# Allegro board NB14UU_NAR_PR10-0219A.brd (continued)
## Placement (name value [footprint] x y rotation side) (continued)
CZ128  0.1U_0201_10V6K  [C_0201]  269.49 56.31 270 top
CZ129  0.1U_0201_10V6K  [C_0201]  239.73 36.4 180 top
CZ130  470P_0402_50V7K  [C_0402]  240.48 37.6 90 top
CZ197  470P_0402_50V7K  [C_0402]  275.84 68.2 90 top
CZ198  100P_0402_50V8J  [C_0402]  261.54 81.61 180 top
CZ200  0.1U_0402_25V6K  [C_0402]  278.44 121 90 top
CZ202  0.1U_0201_10V6K  [C_0201]  127.81 130.86 180 top
CZ203  0.1U_0201_10V6K  [C_0201]  124.43 130.06 0 top
CZ204  15P_0402_50V8J  [C_0402]  286.44 40.64 90 top
CZ205  15P_0402_50V8J  [C_0402]  289.11 40.64 90 top
CZ206  100P_0402_50V8J~D  [C_0402]  288.22 40.64 90 top
CZ207  100P_0402_50V8J~D  [C_0402]  287.33 40.64 90 top
CZ216  0.1U_0201_10V6K  [C_0201]  280.68 73.35 180 top
CZ217  0.1U_0201_10V6K  [C_0201]  283.79 82.62 270 top
CZ218  2.2U_0603_10V6K  [C_0603]  239.2 111.94 270 top
CZ220  0.1U_0402_25V6K  [C_0402]  132.06 122.08 0 top
CZ303  0.1U_0201_10V6K  [C_0201]  171.32 68.15 180 top
CZ305  0.1U_0201_10V6K  [C_0201]  257.11 32.75 270 top
CZ306  470P_0402_50V7K  [C_0402]  255.46 32.79 270 top
CZ309  0.1U_0201_10V6K  [C_0201]  280.27 120.27 90 top
CZ310  0.1U_0201_10V6K  [C_0201]  275.43 92.78 180 top
CZ311  100P_0201_25V8J  [C_0201]  229.24 40.08 90 top
CZ312  100P_0201_25V8J  [C_0201]  226.6 40.38 90 top
CZ313  100P_0201_25V8J  [C_0201]  227.68 36.07 180 top
CZ314  100P_0201_25V8J  [C_0201]  231.35 40.05 90 top
CZ315  100P_0402_50V8J  [C_0402]  222.89 86.43 180 top
CZ316  100P_0402_50V8J  [C_0402]  224.52 82.75 0 top
CZ317  0.1U_0402_25V6  [C_0402]  263.28 56.79 180 top
CZ318  47P_0402_50V8J  [C_0402]  263.28 55.83 180 top
CZ319  2.2P_0402_50V8C  [C_0402]  263.28 54.89 180 top
CZ320  0.1U_0402_25V6  [C_0402]  281.24 89.42 270 top
CZ321  1U_0402_25V6K  [C_0402]  282.18 89.42 270 top
CZ322  100P_0402_50V8J  [C_0402]  283.09 89.42 270 top
DA1  AZ5123-02S.R7G_SOT23-3  [L03ESDL5V0CC3-2_SOT23-3]  299.88 32.52 270 top
DA2  AZ5125-02S.R7G 3P C/A SOT23  [L03ESDL5V0CC3-2_SOT23-3]  299.91 32.52 90 bottom
DA3  AZ5123-02S.R7G_SOT23-3  [L03ESDL5V0CC3-2_SOT23-3]  299.91 37.79 90 bottom
DA4  -  [1N4148WS-L_SOD323-2]  292.79 58.11 90 top
DA5  -  [1N4148WS-L_SOD323-2]  294.44 58.11 90 top
DA6  AZ5125-02S.R7G 3P C/A SOT23  [L03ESDL5V0CC3-2_SOT23-3]  289.75 33.01 0 top
DA7  AZ5125-02S.R7G 3P C/A SOT23  [L03ESDL5V0CC3-2_SOT23-3]  285.81 33.01 0 top
DA8  RB751S40T1G_SOD523-2  [RB520SM-30T2R_EMD2-2]  278.42 44.9 0 top
DC1  RB751540_SOD523  [RB520SM-30T2R_EMD2-2]  200.6 75.72 0 top
DC2  RB751540_SOD523  [RB520SM-30T2R_EMD2-2]  202.3 74.51 180 top
DC4  -  [RB521CM-30T2R_SOD923-2]  205.21 102.05 180 bottom
DE1  BZV55-B5V6_SOD80C2  [BZV55-B5V1_SOD80C2]  85.15 54.93 0 bottom
DE2  RB751S40T1G_SOD523-2  [RB520SM-30T2R_EMD2-2]  244.57 124.66 0 top
DE22  -  [CEST523NC5VB_SOT-523-3]  82.46 59.47 270 top
DI1  -  [AZ1045-04F_DFN2510P10E-10-9]  18.96 88.67 90 bottom
DI2  -  [AZC199-02SPR7G_SOT23-3]  25.87 89.86 90 top
DI3  -  [AZC199-02SPR7G_SOT23-3]  298.76 52.12 180 bottom
DI4  -  [AZ1045-04F_DFN2510P10E-10-9]  300.09 67.49 270 bottom
DI5  -  [AZC199-02SPR7G_SOT23-3]  298.15 64.08 90 top
DI6  -  [AZ1045-04F_DFN2510P10E-10-9]  300.22 50.22 270 bottom
DT1  -  [1N4148WS-7-F_SOD323-2]  59.95 123.9 0 top
DT2  -  [1N4148WS-7-F_SOD323-2]  59.95 122.12 0 top
DT3  -  [1N4148WS-7-F_SOD323-2]  59.95 120.22 0 top
DT4  -  [L30ESD24VC3-2_SOT23-3]  24.8 97.93 90 top
DT5  DESD3V3Z1BCSF-7 X2-DSN0603-2  [ESD8011MUT5G_X3DFN2-2]  14.8 103.89 270 bottom
DT6  DESD3V3Z1BCSF-7 X2-DSN0603-2  [ESD8011MUT5G_X3DFN2-2]  14.8 104.6 90 bottom
DT9  DESD3V3Z1BCSF-7 X2-DSN0603-2  [ESD8011MUT5G_X3DFN2-2]  15.88 107.62 90 bottom
DT10  DESD3V3Z1BCSF-7 X2-DSN0603-2  [ESD8011MUT5G_X3DFN2-2]  15.88 106.91 270 bottom
DT13  DESD3V3Z1BCSF-7 X2-DSN0603-2  [ESD8011MUT5G_X3DFN2-2]  14.8 103.89 270 top
DT14  DESD3V3Z1BCSF-7 X2-DSN0603-2  [ESD8011MUT5G_X3DFN2-2]  14.8 104.6 90 top
DT17  DESD3V3Z1BCSF-7 X2-DSN0603-2  [ESD8011MUT5G_X3DFN2-2]  15.88 107.62 90 top
DT18  DESD3V3Z1BCSF-7 X2-DSN0603-2  [ESD8011MUT5G_X3DFN2-2]  15.88 106.91 270 top
DT39  -  [AZ1045-04F_DFN2510P10E-10-9]  20.63 100.22 90 top
DT40  -  [AZ1045-04F_DFN2510P10E-10-9]  20.63 102.22 270 bottom
DT41  -  [AZ1045-04F_DFN2510P10E-10-9]  283.27 116.69 90 top
DT42  -  [AZ1045-04F_DFN2510P10E-10-9]  283.27 119.77 90 top
DV1  -  [BAT54CW_SOT323-3]  138.11 133.11 180 top
DV2  -  [BAT54CW_SOT323-3]  140.9 133.11 180 top
DV3  -  [BAT54CW_SOT323-3]  157.48 131.58 0 top
DV11  RB751S40T1G_SOD523-2  [RB520SM-30T2R_EMD2-2]  139.34 130.38 180 top
DV12  RB751S40T1G_SOD523-2  [RB520SM-30T2R_EMD2-2]  143.7 130.8 90 top
DV13  AZ5125-02S.R7G 3P C/A SOT23  [L03ESDL5V0CC3-2_SOT23-3]  123.43 126.36 0 top
DV14  -  [AZC199-02SPR7G_SOT23-3]  136.61 127.2 90 top
DZ1  RB751S40T1G_SOD523-2  [RB520SM-30T2R_EMD2-2]  265.03 46.17 0 top
DZ2  RB751S40T1G_SOD523-2  [RB520SM-30T2R_EMD2-2]  265.03 44.9 0 top
DZ5  RB751S40T1G_SOD523-2  [RB520SM-30T2R_EMD2-2]  262.57 83.22 270 top
DZ6  RB751S40T1G_SOD523-2  [RB520SM-30T2R_EMD2-2]  266.38 83.35 270 top
DZ8  -  [RB751S40T1G_SOD523-2]  224.54 37.5 270 top
DZ9  -  [BAT54CW_SOT323-3]  266.5 72.4 180 top
DZ10  -  [AZC199-02SPR7G_SOT23-3]  118.42 124.43 180 top
DZ11  -  [AZC199-02SPR7G_SOT23-3]  296.25 115.2 90 top
DZ12  RB751S40T1G_SOD523-2  [RB520SM-30T2R_EMD2-2]  241.65 113.23 180 top
DZ13  -  [AZ1045-04F_DFN2510P10E-10-9]  300.48 22.28 270 top
FD1  FIDUCIAL MARK~D  [FIDUCIAL_C40M80]  21.14 112.21 0 top
FD2  FIDUCIAL MARK~D  [FIDUCIAL_C40M80]  306 2.74 0 top
FD3  FIDUCIAL MARK~D  [FIDUCIAL_C40M80]  42.74 113.07 180 bottom
FD4  FIDUCIAL MARK~D  [FIDUCIAL_C40M80]  306 2.8 180 bottom
FV1  1A_65V_T0603FF1000TM  [F_T0603FF1000TM]  123.35 130.67 180 top
FZ1  1A_65V_T0603FF1000TM  [F_T0603FF1000TM]  97.89 129.56 90 bottom
FZ2  1A_65V_T0603FF1000TM  [F_T0603FF1000TM]  135.01 134.73 270 top
FZ3  1A_65V_T0603FF1000TM  [F_T0603FF1000TM]  131.22 128.32 90 top
FZ4  1A_65V_T0603FF1000TM  [F_T0603FF1000TM-NPM]  130.9 126.95 180 top
FZ5  1A_65V_T0603FF1000TM  [F_T0603FF1000TM-NPM]  127.59 126.21 90 top
H1  -  [H_4P0]  128.53 111.5 0 top
H2  -  [H_4P0]  192.52 111.5 0 top
H3  -  [H_4P0]  128.53 86.5 0 top
H4  -  [H_4P0]  192.52 86.5 0 top
H7  -  [H_3P2]  268.82 120 0 top
H8  -  [H_3P2]  281.95 67.05 0 top
H11  -  [H_3P3]  118.32 129 0 top
H12  -  [H_3P3]  152.72 129 0 top
H13  H_3P0  [H_3P0-G]  315.03 4 0 top
H14  H_4P0  [H_4P0-G]  301.03 76.5 0 top
H15  -  [H_3P3]  301.52 120 0 top
H16  H_2P6  [H_2P6-G]  249.53 134 0 top
H17  -  [H_3P8]  159.52 136 0 top
H18  H_2P6  [H_2P6-G]  69.52 134 0 top
H20  H_2P6  [H_2P6-G]  15.93 112.4 0 top
H21  -  [H_2P1N]  299.52 43 0 top
H22  -  [H_5P0N]  159.52 32.35 0 top
H25  H_4P0  [H_4P0-G]  80.52 33 0 top
H26  H_4P0  [H_4P0-G]  77.52 91.2 0 top
H27  -  [H_3P1X2P1N]  8.02 80 0 top
H28  H_4P0  [H_4P0-G]  258.53 26.5 0 top
H29  H_4P0  [H_4P0-G]  291.02 120.5 0 top
H30  H_2P6  [H_2P6-G]  3.02 79.5 0 top
JAPS1  ACES_50506-01841-P01  [ACES_50506-01841-P01_18P]  245.74 84.15 180 bottom
JDB1  JXT_FP241AH-006GAAM  [JXT_FP241AH-006GAAM_6P]  33.31 88.93 180 bottom
JDEG1  JXT_FP241AH-010GAAM  [JXT_FP241AH-010GAAM_10P]  218.97 82.87 180 bottom
JDIMM1  LOTES_ADDR0206-P001A  [FOX_ASAA821-H4RB5-7H_260P]  101.45 55.01 180 bottom
JDIMM2  LOTES_ADDR0206-P001A  [FOX_ASAA821-H4RB5-7H_260P]  178.85 51.01 180 bottom
JEDP1  ACES_50398-04041-001  [ACES_50398-04041-001_40P]  125.77 131.02 0 bottom
JESPI  JXT_FP241AH-010GAAM  [JXT_FP241AH-010GAAM_10P]  227.99 82.87 180 bottom
JFAN1  ACES_50271-0040N-001  [ACES_50271-0040N-001_4P]  77.12 64.3 180 bottom
JFPBTN1  FOX_QT510166-L010-7H  [FOX_QT510166-L010-7H_16P]  307.87 116.35 270 bottom
JHDMI1  YUQIU_HD074-F19M1BR-C  [YUQIU_HD074-F19M1BR-C_19P-T]  307.45 89.65 270 bottom
JHP1  SINGA_2SJ3095-136111F~D  [SINGA_2SJ3095-136111F_6P]  306.25 39.35 90 bottom
JIRTS1  ACES_50208-01001-P03  [ACES_50208-01001-P03_10P]  110.22 133.5 180 bottom
JKBTP1  HRS_TF31-20S-0P5SH-800  [HRS_TF31-20S-0P5SH-800_20P-T]  183.49 39.9 0 bottom
JLED1  HRS_TF31-6S-0P5SH  [HRS_TF31-6S-0P5SH_6P-T]  309.07 10.65 180 bottom
JLOM1  SINGA_2RJ3081-1C8211F  [SINGA_2RJ3081-1C8211F_12P-T]  306.2 100.28 90 top
JNGFF1  LOTES_APCI0128-P005A  [LOTES_APCI0128-P005A_75P]  272.7 33.52 0 bottom
JNGFF2  BELLW_80149-3221  [BELLW_80149-3221_67P]  259.58 74.47 0 bottom
JNGFF3  LOTES_APCI0079-P005A  [LOTES_APCI0079-P005A_75P]  282.82 28.77 180 bottom
JRTC1  ACES_50271-0020N-001  [ACES_50271-0020N-001_2P]  239.72 121.2 0 bottom
JSATA1  GS12206-10100-7H  [FOX_GS12206-10100-7H_20P-T]  244.04 38.52 0 bottom
JSD1  T-SOL_158-1240902600  [T-SOL_158-1240902600_23P-T]  304.6 22.86 90 top
JSIM1  JAE_SF51S006V4DR1000Q  [JAE_SF51S006V4DR1000Q_8P]  303.28 24.83 270 bottom
JSPI1  ACES_50506-02041-P01  [ACES_50506-02041-P01_20P]  208.58 84.4 180 bottom
JSPK1  ACES_50278-00401-001  [ACES_50278-00401-001_4P]  293.81 28.14 180 bottom
JTAG1  @SHORT PADS~D  [SHORTPADS]  246.44 105.74 180 top
JUSB1  C-K_26230A-8K1A-02~D  [C-K_26230A-8K1A-02_9P]  302.93 62.9 270 bottom
JUSB2  C-K_26230A-8K1A-02~D  [C-K_26230A-8K1A-02_9P]  16.12 94.2 90 bottom
JUSB3  C-K_26230A-8K1A-02~D  [C-K_26230A-8K1A-02_9P]  302.93 45.7 270 bottom
JUSBC1  JAE_DX07SD24JJ2R1300~D  [JAE_DX07SD24JJ2R1300_24P]  7.35 109.82 270 top
JUSH1  HRS_TF31C-26S-0P5SH-800  [HRS_TF31C-26S-0P5SH-800_26P-T]  224.27 39.9 0 bottom
JXDP1  JXT_FP270H-061G1AM  [JXT_FP270H-061G1AM_61P]  76.17 134.19 0 bottom
LA5  BLM15PX600SN1D_2P  [MURAT_BLM15PX600SN1D_2P]  290.06 61.62 90 top
LA6  BLM15PX800SN1D_2P  [MURAT_BLM15PD800SN1D_2P]  290.51 37.71 270 top
LA7  BLM15PX800SN1D_2P  [MURAT_BLM15PD800SN1D_2P]  288.79 37.71 270 top
LA8  BLM15PX800SN1D_2P  [MURAT_BLM15PD800SN1D_2P]  286.76 37.71 270 top
LA9  BLM15PX800SN1D_2P  [MURAT_BLM15PD800SN1D_2P]  284.86 37.71 270 top
LA10  BLM15PX330SN1D_2P  [MURAT_BLM15PX330SN1D_2P]  298.06 34.45 90 bottom
LA11  BLM15PX330SN1D_2P  [MURAT_BLM15PX330SN1D_2P]  296.38 38.57 90 bottom
LA12  BLM15PX600SN1D_2P  [MURAT_BLM15PX600SN1D_2P]  289.05 48.31 270 top
LA13  HCB2012KF-121T50_2P  [TAI-T_HCB2012KF-121T50_2P]  277.13 53.54 180 top
LA14  BLM15PX600SN1D_2P  [MURAT_BLM15PX600SN1D_2P]  280.98 47.74 270 top
LA15  BLM15PX330SN1D_2P  [MURAT_BLM15PX330SN1D_2P]  297.24 32.25 270 top
LA16  BLM15PX330SN1D_2P  [MURAT_BLM15PX330SN1D_2P]  297.24 33.68 90 top
LC1  LQM18PN2R2NC0L_2P~D  [MURAT_BLM18EG221SN1D_2P]  174.89 118.67 270 top
LC2  LQM18PN2R2NC0L_2P~D  [MURAT_BLM18EG221SN1D_2P]  196.3 117.46 180 bottom
LC3  LQM18PN2R2NC0L_2P~D  [MURAT_BLM18EG221SN1D_2P]  175.45 125.34 180 top
LC4  BLM18EG221TN1D_2P~D  [MURAT_BLM18EG221SN1D_2P]  194.59 97.22 180 top
LC5  BLM15BD121SN1D_2P~D  [MURAT_BLM15BD121SN1D_2P]  185.56 119.83 0 bottom
LC6  HCB1608KF-121T30  [MURAT_BLM18EG221SN1D_2P]  99.74 130.76 270 bottom
LC7  HCB1608KF-121T30  [MURAT_BLM18EG221SN1D_2P]  146.9 135.33 0 top
LC8  HCB1608KF-121T30  [MURAT_BLM18EG221SN1D_2P]  220.32 88.62 90 top
LC9  HCB1608KF-121T30  [MURAT_BLM18EG221SN1D_2P]  264.74 36.62 0 top
LC10  HCB1608KF-121T30  [MURAT_BLM18EG221SN1D_2P]  277.32 94.29 90 top
LC11  HCB1608KF-121T30  [MURAT_BLM18EG221SN1D_2P]  94.89 130.39 90 top
LC12  HCB1608KF-121T30  [MURAT_BLM18EG221SN1D_2P]  218.85 88.62 90 top
LED3  LTW-C193DC-C_WHITE  [LED_LTW-C193DC-C_2P]  310.38 121.75 0 top
LGA1  -  [LNG2DMTR_LGA12_2X2]  250.17 35.29 270 top
LI3  DLM0NSN900HY2D_4P  [MURAT_DLM0NSN900HY2D_4P]  27.28 91.39 180 top
LI4  DLM0NSN900HY2D_4P  [MURAT_DLM0NSN900HY2D_4P]  298.39 56.63 270 bottom
LI7  DLM0NSN900HY2D_4P  [MURAT_DLM0NSN900HY2D_4P]  292.79 66.41 270 top
LI8  MCM1012B900F06BP_4P  [INPAQ_MCM1012B900F06BP_4P]  263.63 72.61 180 bottom
LI9  MCM1012B900F06BP_4P  [INPAQ_MCM1012B900F06BP_4P-NPM]  267.3 34.61 270 bottom
LI12  BLM15BB100SN1D  [MURAT_BLM15BD121SN1D_2P]  267.1 34.42 270 bottom
LI13  BLM15BB100SN1D  [MURAT_BLM15BD121SN1D_2P]  267.99 34.42 270 bottom
LI16  HCM1012GH900BP_4P  [INPAQ_HCM1012GH900BP_4P]  262.07 70.56 0 bottom
LI17  HCM1012GH900BP_4P  [INPAQ_HCM1012GH900BP_4P]  261.99 69.04 0 bottom
LL1  4.7UH +-20% MPB201210T-4R7M-NA2  [TAIYO_BRC2012T4R7MD_2P]  272.53 102.26 270 top
LT11  BLM18KG331SN1D_2P  [MURAT_BLM18KG331SN1D_2P]  36.75 107.13 0 top
LT601  BLM18KG331SN1D_2P  [MURAT_BLM18KG331SN1D_2P]  41.08 112.36 270 top
LT602  BLM18KG331SN1D_2P  [MURAT_BLM18KG331SN1D_2P]  39.81 112.36 270 top
LT603  BLM18KG331SN1D_2P  [MURAT_BLM18KG331SN1D_2P]  35.29 102.56 0 top
LT604  BLM18KG331SN1D_2P  [MURAT_BLM18KG331SN1D_2P]  43.62 110.13 270 top
LT605  BLM18KG331SN1D_2P  [MURAT_BLM18KG331SN1D_2P]  35.35 109.23 0 bottom
LV1  BLM15PX221SN1D_2P  [MURAT_BLM15PX221SN1D_2P]  136.33 133 90 top
LV3  DLW21SN900HQ2L_0805_4P  [MURAT_DLW21SN900HQ2L0805_4P-NPM]  300.52 89.22 0 top
LV6  DLW21SN900HQ2L_0805_4P  [MURAT_DLW21SN900HQ2L0805_4P-NPM]  300.52 87.31 0 top
LV9  DLW21SN900HQ2L_0805_4P  [MURAT_DLW21SN900HQ2L0805_4P-NPM]  300.52 85.41 0 top
LV12  DLW21SN900HQ2L_0805_4P  [MURAT_DLW21SN900HQ2L0805_4P-NPM]  300.52 83.5 0 top
LZ1  DLM0NSN900HY2D_4P  [MURAT_DLM0NSN900HY2D_4P]  139.04 128.09 180 top
LZ3  HCB1005KF-600T25  [MURAT_BLM15PD600SN1D_2P]  225.58 38.87 0 top
LZ4  HCB1005KF-600T25  [MURAT_BLM15PD600SN1D_2P]  227.73 37.46 90 top
NOREF  -  []  148.83 67.71 0 top
NOREF#2  -  []  291.02 120.5 0 top
NOREF#3  -  []  15.93 112.4 0 top
NOREF#4  -  []  125.89 68.73 0 top
NOREF#5  -  []  159.52 32.35 0 top
NOREF#6  -  []  192.52 86.5 0 top
NOREF#7  -  []  268.82 120 0 top
NOREF#8  -  []  220.94 117.66 0 top
NOREF#9  -  []  127.85 68.1 0 top
NOREF#10  -  []  301.52 120 0 top
NOREF#11  -  []  315.03 4 0 top
NOREF#12  -  []  69.52 134 0 top
NOREF#13  -  []  157.96 -187.65 0 top
NOREF#14  -  []  192.52 111.5 0 top
NOREF#15  -  []  128.53 111.5 0 top
NOREF#16  -  []  118.32 129 0 top
NOREF#17  -  []  80.52 33 0 top
NOREF#18  -  []  281.95 67.05 0 top
NOREF#19  -  []  152.72 129 0 top
NOREF#20  -  []  143.45 31.67 0 top
NOREF#21  -  []  128.53 86.5 0 top
NOREF#22  -  []  301.03 76.5 0 top
NOREF#23  -  []  191.26 61.94 0 top
NOREF#24  -  []  169.07 -43.31 0 top
NOREF#25  -  []  77.52 91.2 0 top
NOREF#26  -  []  212.79 58.33 0 top
NOREF#27  -  []  258.53 26.5 0 top
NOREF#28  -  []  197.77 58.01 270 top
NOREF#29  -  []  249.53 134 0 top
NOREF#30  -  []  368.44 -160.33 180 bottom
NOREF#31  -  []  370.91 67.97 180 bottom
NOREF#32  -  []  150.41 73.81 180 bottom
PBATT1  DEREN_40-42251-01001RHF  [DEREN_40-42251-01001RHF_10P-T]  148.77 42.7 180 bottom
PC1  2200P_0402_50V7K  [C_0402]  140.01 39.88 90 top
PC3  1U_0402_25V6K  [C_0402]  239.83 118.5 90 top
PC4  0.022U 25V K X7R 0402  [C_0402]  78.24 111.71 180 bottom
PC5  1000P_0402_50V7K  [C_0402]  68.77 119.53 270 bottom
PC6  0.022U 25V K X7R 0402  [C_0402]  76.04 118.77 90 bottom
PC7  0.1U_0402_25V6  [C_0402]  74.06 118.78 90 bottom
PC8  10U_0603_25V6M  [C_0603]  75.93 114.67 180 bottom
PC10  4.7U_0402_6.3V6M  [C_0402]  68.84 117.42 180 top
PC11  1000P_0402_50V7K  [C_0402]  75.24 117.61 270 top
PC12  82P_0402_50V8J  [C_0402]  68.84 116.53 180 top
PC13  0.1U_0402_10V7K  [C_0402]  78.67 114.42 90 top
PC100  0.1U_0402_25V6  [C_0402]  196.72 33.53 90 bottom
PC102  0.1U_0402_25V6  [C_0402]  205.99 29.79 90 bottom
PC103  100P_0402_50V8J  [C_0402]  201.23 31.18 90 bottom
PC104  10U_0603_25V6M  [C_0603]  200.15 30.62 90 bottom
PC105  10U_0603_25V6M  [C_0603]  200.15 30.62 90 top
PC106  22U_0603_6.3V6M  [C_0603]  219.2 36.4 90 top
PC107  22U_0603_6.3V6M  [C_0603]  219.2 36.4 90 bottom
PC108  22U_0603_6.3V6M  [C_0603]  220.4 36.4 90 bottom
PC109  22U_0603_6.3V6M  [C_0603]  217.99 36.4 90 bottom
PC110  22U_0603_6.3V6M  [C_0603]  220.4 36.4 90 top
PC111  4.7U_0402_6.3V6M  [C_0402]  205.8 38.38 270 bottom
PC112  680P_0402_50V7K  [C_0402]  201.8 34.87 180 top
PC113  1000P_0402_50V7K  [C_0402]  203.51 37.4 90 bottom
PC114  0.1U_0402_25V6  [C_0402]  85.02 73.98 90 bottom
PC115  0.1U_0402_25V6  [C_0402]  81.03 67.76 180 top
PC116  2200P_0402_50V7K  [C_0402]  81.03 66.88 180 top
PC117  10U_0603_25V6M  [C_0603]  81.28 68.91 180 top
PC118  10U_0603_25V6M  [C_0603]  81.28 68.91 180 bottom
PC119  2.2U 6.3V M X5R 0402  [C_0402]  76.34 73.99 180 bottom
PC120  22U_0603_6.3V6M  [C_0603]  74.99 76.46 270 top
PC121  22U_0603_6.3V6M  [C_0603]  76.26 76.46 270 top
PC122  22U_0603_6.3V6M  [C_0603]  76.26 76.46 270 bottom
PC123  22U_0603_6.3V6M  [C_0603]  73.72 76.46 270 bottom
PC124  22U_0603_6.3V6M  [C_0603]  74.99 76.46 270 bottom
PC125  680P_0402_50V7K  [C_0402]  86.42 81.16 90 bottom
PC126  4.7U_0402_6.3V6M  [C_0402]  76.34 73.1 180 bottom
PC127  1000P_0402_50V7K  [C_0402]  76.34 71.57 180 bottom
PC128  4.7U_0402_6.3V6M  [C_0402]  76.26 70.64 270 bottom
PC129  22U_0603_6.3V6M  [C_0603]  217.99 36.4 90 top
PC130  22U_0603_6.3V6M  [C_0603]  73.72 76.46 270 top
PC131  82P_0402_50V8J  [C_0402]  201.23 31.18 90 top
PC132  82P_0402_50V8J  [C_0402]  81.03 67.76 180 bottom
PC133  100P_0402_50V8J  [C_0402]  198.56 33.53 90 bottom
PC134  100P_0402_50V8J  [C_0402]  197.67 33.53 90 bottom
PC135  100P_0402_50V8J  [C_0402]  215.7 36.45 90 bottom
PC136  27P_0402_50V8J  [C_0402]  215.7 36.45 90 top
PC137  100P_0402_50V8J  [C_0402]  72.58 76.48 270 top
PC138  100P_0402_50V8J  [C_0402]  72.58 76.48 270 bottom
PC139  100P_0402_50V8J  [C_0402]  81.03 65.97 180 top
PC140  100P_0402_50V8J  [C_0402]  81.03 65.07 180 top
PC141  1U_0402_25V6K  [C_0402]  179.57 31.24 90 bottom
PC142  1U_0402_25V6K  [C_0402]  85.66 69.56 270 bottom
PC143  100P_0402_50V8J  [C_0402]  198.65 31.06 90 top
PC145  100P_0402_50V8J  [C_0402]  78.58 76.4 270 top
PC146  22P_0402_50V8J  [C_0402]  86.62 69.57 270 bottom
PC161  22U_0603_6.3V6M  [C_0603]  216.78 36.4 90 bottom
PC162  22U_0603_6.3V6M  [C_0603]  216.78 36.4 90 top
PC163  22U_0603_6.3V6M  [C_0603]  77.53 76.46 270 top
PC164  22U_0603_6.3V6M  [C_0603]  77.53 76.46 270 bottom
PC200  10U_0603_25V6M  [C_0603]  91.38 69.54 0 top
PC201  10U_0603_25V6M  [C_0603]  91.38 69.54 0 bottom
PC202  82P_0402_50V8J  [C_0402]  91.44 70.62 0 top
PC203  0.1U_0402_25V6  [C_0402]  91.44 70.62 0 bottom
PC204  680P_0402_50V7K  [C_0402]  90.86 66.93 90 top
PC205  0.1U_0402_25V6  [C_0402]  85.97 62.18 270 bottom
PC206  1U_0201_6.3V6M  [C_0201]  88.43 64.27 180 bottom
PC207  2.2U 6.3V M X5R 0402  [C_0402]  88.46 65.54 180 bottom
PC208  330P_0402_50V7K  [C_0402]  87.61 67.83 0 bottom
PC209  22U_0603_6.3V6M  [C_0603]  94.81 64.12 0 bottom
PC210  22U_0603_6.3V6M  [C_0603]  95.31 55.83 270 top
PC211  22U_0603_6.3V6M  [C_0603]  95.31 55.83 270 bottom
PC212  22U_0603_6.3V6M  [C_0603]  94.04 55.83 270 top
PC213  22U_0603_6.3V6M  [C_0603]  94.04 55.83 270 bottom
PC214  10U_0603_10V6M  [C_0603]  92.77 55.83 270 top
PC216  15P_0402_50V8J  [C_0402]  96.39 55.4 270 top
PC217  15P_0402_50V8J  [C_0402]  96.39 55.4 270 bottom
PC218  1U_0201_6.3V6M  [C_0201]  94.79 66.9 270 bottom
PC219  22U_0603_6.3V6M  [C_0603]  94.8 65.38 0 bottom
PC221  0.1U_0402_10V7K  [C_0402]  95.19 70.37 180 bottom
PC222  0.1U_0402_10V7K  [C_0402]  95.26 69.54 180 top
PC223  10U_0603_10V6M  [C_0603]  92.77 55.83 270 bottom
PC224  100P_0402_50V8J  [C_0402]  91.69 55.4 270 top
PC225  100P_0402_50V8J  [C_0402]  91.69 55.4 270 bottom
PC226  1U_0201_6.3V6M  [C_0201]  219.9 30.34 270 bottom
PC227  1U_0201_6.3V6M  [C_0201]  95.36 66.9 270 bottom
PC228  22P 16V K X7R 0201  [C_0201]  221.06 30.34 270 bottom
PC301  18P 50V K NPO 0402  [C_0402]  234.17 125.74 0 bottom
PC302  680P_0402_50V7K  [C_0402]  227.13 130.38 0 bottom
PC303  100P_0402_50V8J  [C_0402]  234.17 126.63 0 bottom
PC304  0.1U_0402_25V6  [C_0402]  230.06 126.44 90 top
PC305  10U_0603_25V6M  [C_0603]  233.11 127.71 0 top
PC306  10U_0603_25V6M  [C_0603]  233.11 127.71 0 bottom
PC307  330P_0402_50V7K  [C_0402]  231.82 135.46 0 top
PC308  22U_0603_6.3V6M  [C_0603]  219.71 132.09 90 top
PC309  22U_0603_6.3V6M  [C_0603]  219.71 132.09 90 bottom
PC310  22U_0603_6.3V6M  [C_0603]  220.98 132.09 90 bottom
PC311  22U_0603_6.3V6M  [C_0603]  220.98 132.09 90 top
PC312  1U_0201_6.3V6M  [C_0201]  230.94 134.22 270 top
PC313  2.2U 6.3V M X5R 0402  [C_0402]  230.06 133.73 90 top
PC314  1U_0201_6.3V6M  [C_0201]  220.47 29.75 90 bottom
PC315  100P_0402_50V8J  [C_0402]  232.33 114.34 0 top
PC316  0.1U_0402_25V6  [C_0402]  232.33 115.28 0 top
PC317  1U_0402_25V6K  [C_0402]  232.33 116.23 0 top
PC318  27P_0402_50V8J  [C_0402]  217.74 132.71 90 top
PC319  100P_0402_50V8J  [C_0402]  218.63 132.71 90 top
PC320  1U_0402_25V6K  [C_0402]  216.85 132.71 90 top
PC330  120P_0402_50V8J  [C_0402]  234.16 124.84 0 bottom
PC331  100P_0402_50V8J  [C_0402]  229.92 125.37 180 top
PC332  100P_0402_50V8J  [C_0402]  227.77 124.38 90 bottom
PC333  1U_0402_25V6K  [C_0402]  229.67 124.37 90 bottom
PC334  18p_0402_50V6  [C_0402]  232.33 117.17 0 top
PC335  0.1U_0402_25V6  [C_0402]  228.72 124.37 90 bottom
PC336  0.1U_0402_25V6  [C_0402]  230.68 127.84 0 bottom
PC337  1U_0402_25V6K  [C_0402]  230.67 126.88 0 bottom
PC338  0.1U_0402_25V6  [C_0402]  232.56 125.04 90 bottom
PC339  0.1U_0402_25V6  [C_0402]  230.67 125.93 0 bottom
PC350  0.022U_ 0402_25V7K  [C_0402]  235.34 130.33 270 top
PC360  0.1U_0402_25V6  [C_0402]  235.31 132.89 0 top
PC401  470P_0402_50V7K  [C_0402]  110.42 78.89 270 top
PC402  0.1U_0402_25V6  [C_0402]  104.78 72.46 180 top
PC403  10U_0603_10V6M  [C_0603]  102.67 74.31 270 top
PC404  10U_0603_10V6M  [C_0603]  101.4 74.31 270 top
PC406  22U_0603_6.3V6M  [C_0603]  110.04 72.53 270 top
PC407  22U_0603_6.3V6M  [C_0603]  108.77 72.53 270 top
PC408  0.1U_0402_25V6  [C_0402]  99.25 74.32 270 top
PC409  100P_0402_50V8J  [C_0402]  100.26 74.32 270 top
PC410  1U_0402_25V6K  [C_0402]  207.96 126.18 90 bottom
PC411  0.1U_0402_25V6  [C_0402]  209.42 133.92 90 top
PC412  10U_0603_10V6M  [C_0603]  212.09 132.03 90 top
PC413  10U_0603_10V6M  [C_0603]  212.09 132.03 90 bottom
PC414  0.1U_0402_25V6  [C_0402]  208.87 126.17 90 bottom
PC415  22U_0603_6.3V6M  [C_0603]  201.1 132.09 90 top
PC416  100P_0402_50V8J  [C_0402]  210.61 126.69 135 bottom
PC417  0.1U_0402_25V6  [C_0402]  213.16 132.01 90 bottom
PC418  2200P_0402_50V7K  [C_0402]  213.16 132.01 90 top
PC419  680P_0402_50V7K  [C_0402]  206.55 130.57 0 bottom
PC420  22P_0402_50V8J  [C_0402]  211.01 132.05 90 bottom
PC421  0.1U_0402_25V6  [C_0402]  210.05 132.05 90 bottom
PC424  22U_0603_6.3V6M  [C_0603]  201.1 132.09 90 bottom
PC425  10U_0402_6.3V6M  [C_0402]  112.2 72.54 270 top
PC426  10U_0402_6.3V6M  [C_0402]  111.18 72.54 270 top
PC427  10U_0402_6.3V6M  [C_0402]  202.24 132.33 90 bottom
PC428  10U_0402_6.3V6M  [C_0402]  202.24 132.33 90 top
PC501  22U_0603_6.3V6M  [C_0603]  199.83 109.67 0 top
PC503  68P_0402_50V8J  [C_0402]  203.96 109.15 90 bottom
PC504  22U_0603_6.3V6M  [C_0603]  199.83 109.67 0 bottom
PC505  .1U_0402_16V7K  [C_0402]  201.48 111.66 270 top
PC506  680P_0402_50V7K  [C_0402]  200.45 114.88 0 bottom
PC507  4.7U_0402_6.3V6M  [C_0402]  281.92 95.58 0 top
PC508  4.7U_0402_6.3V6M  [C_0402]  281.92 94.69 0 top
PC509  0.01UF_0402_25V7K  [C_0402]  286.63 96.52 90 top
PC510  0.1U_0402_25V6  [C_0402]  280.03 98.87 90 top
PC511  22U_0603_6.3V6M  [C_0603]  285.72 95.39 180 top
PC513  .1U_0402_16V7K  [C_0402]  243.54 62.45 0 top
PC514  4.7U_0402_6.3V6M  [C_0402]  240.82 61.57 270 top
PC515  0.01UF_0402_25V7K  [C_0402]  242.98 55.83 90 top
PC516  22U_0603_6.3V6M  [C_0603]  240.56 57.62 90 top
PC517  4.7U_0402_6.3V6M  [C_0402]  239.67 61.57 270 top
PC530  22U_0603_6.3V6M  [C_0603]  202.67 114.69 0 bottom
PC601  680P_0402_50V7K  [C_0402]  96.41 93.7 90 top
PC602  0.1U_0402_25V6  [C_0402]  87.65 101.45 90 bottom
PC603  4.7U_0402_6.3V6M  [C_0402]  91.33 101.45 90 top
PC604  1U_0402_25V6K  [C_0402]  92.79 101.27 0 top
PC605  47P_0402_50V8J  [C_0402]  84.31 102.31 0 top
PC606  100U_D_20VM_R55M  [C_D]  93.21 107.51 90 bottom
PC607  100U_D_20VM_R55M  [C_D]  88.51 107.51 90 bottom
PC608  10U 25V M X5R 0603 ZRB  [C_0603-S3]  178.05 129.74 180 top
PC611  0.22U 25V K X5R 0402  [C_0402]  180.27 131.58 270 top
PC612  10U 25V M X5R 0603 ZRB  [C_0603-S3]  178.05 129.74 180 bottom
PC613  330P_0402_50V7K  [C_0402]  85.75 100.2 270 top
PC614  2200P_0402_50V7K  [C_0402]  87.43 95.76 90 bottom
PC616  68P 50V J NPO 0402  [C_0402]  86.55 95.76 90 bottom
PC617  1200P_0402_50V7K  [C_0402]  81.94 97.89 90 top
PC618  330P_0402_50V7K  [C_0402]  80.92 97.91 270 top
PC619  0.01UF_0402_25V7K  [C_0402]  80.92 95.22 90 top
PC620  0.082U_0402_16V7K  [C_0402]  81.94 97.03 270 top
PC621  680P_0402_50V7K  [C_0402]  83 99.74 0 top
PC622  680P_0402_50V7K  [C_0402]  178.62 131.9 90 bottom
PC624  0.022U_0402_25V7K  [C_0402]  83.84 95.37 270 top
PC625  330P_0402_50V7K  [C_0402]  86.38 89 90 top
PC626  0.1U_0402_25V6  [C_0402]  82.95 95.37 270 top
PC627  2200P_0402_50V7K  [C_0402]  85.62 93.83 90 top
PC628  33P_0402_50V8J  [C_0402]  92.81 96.7 180 bottom
PC629  2200P_0402_50V7K  [C_0402]  88.96 94.89 270 bottom
PC630  2200P_0402_50V7K  [C_0402]  94.25 92.71 270 top
PC631  4700P_0402_25V7K  [C_0402]  92.81 97.58 180 bottom
PC632  1000P_0402_50V7K  [C_0402]  94.51 97.89 90 top
PC633  4700P 25V K X7R 0402  [C_0402]  172.55 129.47 180 top
PC635  0.022U_0402_16V7K  [C_0402]  85.24 91.29 90 top
PC636  33P_0402_50V8J  [C_0402]  90.48 94.89 270 bottom
PC637  0.033U_0402_25V7K  [C_0402]  96.29 97.89 90 top
PC638  0.022U_0402_16V7K  [C_0402]  86.13 91.29 90 top
PC639  1500P_0402_50V7K  [C_0402]  89.89 89.84 180 top
PC640  2200P_0402_50V7K  [C_0402]  95.4 95.48 90 top
PC641  .1U_0402_16V7K  [C_0402]  82.95 93.6 270 top
PC642  0.068U_0402_16V7K  [C_0402]  91.51 92.76 0 top
PC643  330P_0402_50V7K  [C_0402]  92.81 95.81 180 bottom
PC644  .1U_0402_16V7K  [C_0402]  96.21 99.74 0 top
PC645  .1U_0402_16V7K  [C_0402]  92.6 90.8 270 top
PC646  6800P 50V K X7R 0402  [C_0402]  91.51 91.74 0 top
PC647  680P_0402_50V7K  [C_0402]  88.03 89.91 270 top
PC649  0.01UF_0402_25V7K  [C_0402]  97.43 96.37 90 top
PC650  0.082U_0402_16V7K  [C_0402]  96.41 96.52 270 top
PC651  330P_0402_50V7K  [C_0402]  89.86 88.95 0 top
PC652  330P_0402_50V7K  [C_0402]  97.43 95.5 270 top
PC653  0.082U_0402_16V7K  [C_0402]  90.75 89.84 0 top
PC654  0.01UF_0402_25V7K  [C_0402]  92.55 88.95 180 top
PC655  0.22U_0402_25V6K  [C_0402]  114.11 96.47 90 bottom
PC656  10U 25V M X5R 0603 ZRB  [C_0603-S3]  110.23 100.72 90 bottom
PC657  10U 25V M X5R 0603 ZRB  [C_0603-S3]  110.23 100.72 90 top
PC658  10U 25V M X5R 0603 ZRB  [C_0603-S3]  111.44 100.72 90 top
PC659  0.1U_0402_25V6  [C_0402]  112.52 101.22 90 top
PC660  2200P_0402_50V7K  [C_0402]  109.15 101.22 90 bottom
PC661  4.7U_0402_6.3V6M  [C_0402]  120.01 100.96 90 bottom
PC662  680P_0402_50V7K  [C_0402]  113.53 105.74 180 top
PC663  0.22U_0402_25V6K  [C_0402]  101.28 90.11 0 bottom
PC664  10U 25V M X5R 0603 ZRB  [C_0603-S3]  105.41 93.99 0 bottom
PC665  10U 25V M X5R 0603 ZRB  [C_0603-S3]  105.41 93.99 0 top
PC666  100P_0402_50V8J  [C_0402]  105.33 90.74 0 top
PC667  1U_0402_25V6K  [C_0402]  105.33 91.7 0 top
PC668  4.7U_0402_6.3V6M  [C_0402]  105.84 84.2 0 bottom
PC669  4.7U_0402_6.3V6M  [C_0402]  102.48 86.69 90 bottom
PC670  680P_0402_50V7K  [C_0402]  110.87 89.86 180 top
PC671  0.22U_0402_25V6K  [C_0402]  100.13 101.42 90 bottom
PC672  10U 25V M X5R 0603 ZRB  [C_0603-S3]  96.2 106.98 90 bottom
PC673  10U 25V M X5R 0603 ZRB  [C_0603-S3]  96.2 106.97 90 top
PC674  10U 25V M X5R 0603 ZRB  [C_0603-S3]  105.41 92.78 0 top
PC675  10U 25V M X5R 0603 ZRB  [C_0603-S3]  105.41 92.78 0 bottom
PC676  4.7U_0402_6.3V6M  [C_0402]  117.47 97.67 180 bottom
PC677  4.7U_0402_6.3V6M  [C_0402]  103.51 102.58 180 bottom
PC678  680P_0402_50V7K  [C_0402]  99.44 110.06 180 top
PC682  10U 25V M X5R 0603 ZRB  [C_0603-S3]  111.44 100.72 90 bottom
PC683  10U 25V M X5R 0603 ZRB  [C_0603-S3]  97.4 106.97 90 bottom
PC684  10U 25V M X5R 0603 ZRB  [C_0603-S3]  97.39 106.97 90 top
PC685  4.7U_0402_6.3V6M  [C_0402]  182.88 134.87 90 top
PC686  0.1U_0402_25V6  [C_0402]  112.52 101.22 90 bottom
PC687  0.1U_0402_25V6  [C_0402]  105.65 91.7 0 bottom
PC688  0.1U_0402_25V6  [C_0402]  98.5 107.06 90 bottom
PC689  100P_0402_50V8J  [C_0402]  91.8 82.95 90 bottom
PC690  100P_0402_50V8J  [C_0402]  92.76 82.95 90 bottom
PC691  1U_0402_25V6K  [C_0402]  90.85 82.95 90 bottom
PC692  22P_0402_50V8J  [C_0402]  89.9 82.95 90 bottom
PC693  100P_0402_50V8J  [C_0402]  95.11 107 90 top
PC694  18P 50V K 0402  [C_0402]  94.14 107 90 top
PC697  4.7U_0402_6.3V6M  [C_0402]  106.04 105.92 90 bottom
PC700  0.1U_0402_25V6  [C_0402]  100.69 37.5 0 top
PC701  2200P_0402_50V7K  [C_0402]  100.69 36.18 0 top
PC702  10U_0805_25VAK  [C_0805]  100.36 30.87 0 top
PC703  10U_0805_25VAK  [C_0805]  100.36 32.59 0 top
PC704  10U_0805_25VAK  [C_0805]  100.49 39.76 0 top
PC706  10U_0805_25VAK  [C_0805]  100.36 32.59 0 bottom
PC707  10U_0603_25V6M  [C_0603]  124.84 33.22 180 bottom
PC708  10U_0603_25V6M  [C_0603]  124.84 34.49 180 bottom
PC709  10U_0603_25V6M  [C_0603]  124.84 34.49 180 top
PC710  10U_0603_25V6M  [C_0603]  124.84 33.22 180 top
PC715  15U_B2_25VM_R100M  [C_B2]  125.26 30.93 0 bottom
PC716  10U_0805_25VAK  [C_0805]  100.49 39.76 0 bottom
PC717  10U_0805_25VAK  [C_0805]  100.36 30.87 0 bottom
PC719  4.7U_0402_6.3V6M  [C_0402]  81.9 43.06 0 bottom
PC720  0.1U_0402_25V6  [C_0402]  124.72 36.53 180 top
PC721  2200P_0402_50V7K  [C_0402]  124.72 39.17 180 top
PC725  1U_0402_25V6K  [C_0402]  81.87 42.15 180 bottom
PC726  1U_0402_25V6K  [C_0402]  82.74 42.15 0 bottom
PC727  0.47U 25V K X5R 0402  [C_0402]  86.05 41.96 270 bottom
PC728  0.1U_0201_25V6K  [C_0201]  125.83 42.01 45 top
PC729  0.1U_0201_25V6K  [C_0201]  123.57 40.97 225 top
PC730  0.1U_0201_25V6K  [C_0201]  125.43 42.41 45 top
PC731  82P_0201_50V8J  [C_0201]  123.14 41.4 225 top
PC732  82P_0201_50V8J  [C_0201]  125.01 42.83 45 top
PC733  82P_0201_50V8J  [C_0201]  121.05 41.73 270 top
PC734  22P 16V K X7R 0201  [C_0201]  124.59 43.26 45 top
PC735  2200P 16V K X7R 0201  [C_0201]  121.64 41.73 270 top
PC736  0.1U_0402_25V6  [C_0402]  81.66 46.91 0 top
PC737  2.2U_0402_25V6M  [C_0402]  79.81 43.13 90 top
PC738  4.7U_0402_6.3V6M  [C_0402]  87.69 44.05 0 bottom
PC739  4.7U_0402_6.3V6M  [C_0402]  88.59 43.13 270 bottom
PC740  0.47U 25V K X5R 0402  [C_0402]  88.53 46.85 0 bottom
PC741  10U_0603_25V6M  [C_0603]  128.77 39.8 90 top
PC742  10U_0603_25V6M  [C_0603]  128.77 39.8 90 bottom
PC743  4700P_0402_25V7K  [C_0402]  130.22 36.14 0 top
PC744  10P_0402_50V8J  [C_0402]  81.71 48.59 0 top
PC745  0.1U_0402_25V6  [C_0402]  88.45 48.75 0 bottom
PC746  680P_0402_50V7K  [C_0402]  104.96 42.62 270 bottom
PC747  680P_0402_50V7K  [C_0402]  122.42 41.86 0 bottom
PC748  1U_0402_25V6K  [C_0402]  88.07 50.73 0 bottom
PC749  560P_0402_50V7K  [C_0402]  84.21 50.84 90 bottom
PC750  0.1U_0402_25V6  [C_0402]  85.1 50.84 90 bottom
PC751  0.01UF_0402_25V7K  [C_0402]  82.42 51.67 0 bottom
PC752  1U_0402_25V6K  [C_0402]  88.1 49.83 180 bottom
PC753  0.22U_0402_25V6K  [C_0402]  87.21 50.73 180 bottom
PC754  0.1U_0402_10V7K  [C_0402]  76.39 42.16 90 bottom
PC755  0.1U_0402_25V6  [C_0402]  85.42 49.11 270 top
PC756  100P_0402_50V8J  [C_0402]  100.76 41.09 0 bottom
PC760  100P_0402_50V8J  [C_0402]  124.62 30.69 180 top
PC761  18p_0402_50V6  [C_0402]  124.75 37.84 180 top
PC800  100P_0402_50V8J  [C_0402]  54.11 85.93 180 bottom
PC801  0.01UF_0402_25V7K  [C_0402]  60.59 84.15 180 bottom
PC802  1500P_0402_50V7K  [C_0402]  77.72 110.81 90 top
PC803  0.47U 25V K X5R 0402  [C_0402]  68.98 106.88 0 top
PC804  220P_0402_50V8J  [C_0402]  56.02 88.72 180 bottom
PC805  1200P_0402_50V7K  [C_0402]  56.65 83.77 180 bottom
PC806  100P_0402_50V8J  [C_0402]  19.88 95.16 180 top
PC807  1000P_0402_50V7K  [C_0402]  19.88 96.05 180 top
PC808  0.1U_0402_25V6  [C_0402]  20.07 91.96 180 top
PC809  100P_0402_50V8J  [C_0402]  20.07 92.85 180 top
PC810  1500P_0402_50V7K  [C_0402]  48.83 91.31 90 top
PC811  10U_0402_6.3V M  [C_0402]  61.53 87.5 90 bottom
PC812  100P_0402_50V8J  [C_0402]  59.67 88.59 0 bottom
PC813  2.2U_0402_25V6M  [C_0402]  61.53 85.88 270 bottom
PC814  0.1U_0402_10V7K  [C_0402]  83.62 103.02 270 bottom
PC865  0.1U_0402_25V6  [C_0402]  89.22 114.43 270 top
PC1000  22U_0603_6.3V6M  [C_0603]  164.52 101.8 270 top
PC1001  22U_0603_6.3V6M  [C_0603]  163.32 101.8 270 top
PC1002  22U_0603_6.3V6M  [C_0603]  122.04 111.33 0 bottom
PC1003  22U_0603_6.3V6M  [C_0603]  122.04 111.33 0 top
PC1004  22U_0603_6.3V6M  [C_0603]  108.52 110.94 270 top
PC1005  22U_0603_6.3V6M  [C_0603]  108.52 110.94 270 bottom
PC1006  22U_0603_6.3V6M  [C_0603]  122.04 112.6 0 top
PC1007  22U_0603_6.3V6M  [C_0603]  122.04 112.6 0 bottom
PC1008  22U_0603_6.3V6M  [C_0603]  162.11 98.05 90 top
PC1009  22U_0603_6.3V6M  [C_0603]  162.11 101.81 270 top
PC1011  22U_0603_6.3V6M  [C_0603]  164.52 98.05 90 top
PC1012  22U_0603_6.3V6M  [C_0603]  156.94 122.47 90 bottom
PC1013  22U_0603_6.3V6M  [C_0603]  160.9 98.05 90 top
PC1014  22U_0603_6.3V6M  [C_0603]  159.7 98.05 90 top
PC1015  22U_0603_6.3V6M  [C_0603]  159.7 101.8 270 top
PC1016  22U_0603_6.3V6M  [C_0603]  155.74 122.47 90 top
PC1017  22U_0603_6.3V6M  [C_0603]  155.74 122.47 90 bottom
PC1018  22U_0603_6.3V6M  [C_0603]  160.9 101.79 270 top
PC1019  22U_0603_6.3V6M  [C_0603]  163.32 98.05 90 top
PC1020  22U_0603_6.3V6M  [C_0603]  156.94 122.47 90 top
PC1031  1U_0201_6.3V6M  [C_0201]  161.32 94.18 180 top
PC1032  1U_0201_6.3V6M  [C_0201]  165.63 104.79 0 top
PC1033  1U_0201_6.3V6M  [C_0201]  161.95 94.18 0 top
PC1034  1U_0201_6.3V6M  [C_0201]  165.54 94.21 90 top
PC1035  1U_0201_6.3V6M  [C_0201]  164.36 94.18 0 top
PC1036  1U_0201_6.3V6M  [C_0201]  159.32 102.65 90 top
PC1037  1U_0201_6.3V6M  [C_0201]  163.74 94.75 180 top
PC1038  1U_0201_6.3V6M  [C_0201]  164.36 94.75 0 top
PC1039  1U_0201_6.3V6M  [C_0201]  158.91 94.75 180 top
PC1040  1U_0201_6.3V6M  [C_0201]  157.12 94.18 0 top
PC1041  1U_0201_6.3V6M  [C_0201]  162.21 93.61 180 top
PC1042  1U_0201_6.3V6M  [C_0201]  158.91 94.18 180 top
PC1043  1U_0201_6.3V6M  [C_0201]  156.87 105.36 0 top
PC1044  1U_0201_6.3V6M  [C_0201]  153.83 105.36 180 top
PC1045  1U_0201_6.3V6M  [C_0201]  156.24 105.36 180 top
PC1046  1U_0201_6.3V6M  [C_0201]  154.45 104.79 0 top
PC1047  1U_0201_6.3V6M  [C_0201]  153.83 104.79 180 top
PC1048  1U_0201_6.3V6M  [C_0201]  149.63 104.79 0 top
PC1049  1U_0201_6.3V6M  [C_0201]  159.53 94.18 0 top
PC1050  1U_0201_6.3V6M  [C_0201]  159.53 94.75 0 top
PC1051  1U_0201_6.3V6M  [C_0201]  156.87 104.79 0 top
PC1052  1U_0201_6.3V6M  [C_0201]  151.42 104.79 180 top
PC1053  1U_0201_6.3V6M  [C_0201]  152.04 105.36 0 top
PC1054  1U_0201_6.3V6M  [C_0201]  161.69 105.36 0 top
PC1055  1U_0201_6.3V6M  [C_0201]  156.24 104.79 180 top
PC1056  1U_0201_6.3V6M  [C_0201]  154.45 105.36 0 top
PC1057  1U_0201_6.3V6M  [C_0201]  159.28 104.79 0 top
PC1058  1U_0201_6.3V6M  [C_0201]  159.28 105.36 0 top
PC1059  1U_0201_6.3V6M  [C_0201]  158.66 104.79 180 top
PC1060  1U_0201_6.3V6M  [C_0201]  163.22 104.79 0 top
PC1061  1U_0201_6.3V6M  [C_0201]  165.01 105.36 180 top
PC1062  1U_0201_6.3V6M  [C_0201]  161.32 94.75 180 top
PC1063  1U_0201_6.3V6M  [C_0201]  158.66 105.36 180 top
PC1064  1U_0201_6.3V6M  [C_0201]  161.07 104.79 180 top
PC1065  1U_0201_6.3V6M  [C_0201]  161.07 105.36 180 top
PC1066  1U_0201_6.3V6M  [C_0201]  161.69 104.79 0 top
PC1067  1U_0201_6.3V6M  [C_0201]  165.01 104.79 180 top
PC1068  1U_0201_6.3V6M  [C_0201]  157.12 94.75 0 top
PC1069  1U_0201_6.3V6M  [C_0201]  161.95 94.75 0 top
PC1070  1U_0201_6.3V6M  [C_0201]  163.22 105.36 0 top
PC1071  47U_0603_6.3V6M  [C_0603-S3]  151.49 102.94 180 top
PC1072  47U_0603_6.3V6M  [C_0603-S3]  152.45 102.93 0 top
PC1073  47U_0603_6.3V6M  [C_0603-S3]  156.19 102.93 180 top
PC1074  47U_0603_6.3V6M  [C_0603-S3]  157.16 102.94 0 top
PC1075  47U_0603_6.3V6M  [C_0603-S3]  161.51 102.97 180 top
PC1076  47U_0603_6.3V6M  [C_0603-S3]  163.1 102.99 0 top
PC1077  47U_0603_6.3V6M  [C_0603-S3]  157.21 96.96 180 top
PC1078  47U_0603_6.3V6M  [C_0603-S3]  159.2 96.95 0 top
PC1079  47U_0603_6.3V6M  [C_0603-S3]  162.95 96.95 180 top
PC1080  47U_0603_6.3V6M  [C_0603-S3]  164.13 96.96 0 top
PC1081  22U_0603_6.3V6M  [C_0603]  109.72 110.94 270 top
PC1082  22U_0603_6.3V6M  [C_0603]  154.53 122.47 90 bottom
PC1083  22U_0603_6.3V6M  [C_0603]  109.72 110.94 270 bottom
PC1084  22U_0603_6.3V6M  [C_0603]  110.93 110.94 270 top
PC1085  22U_0603_6.3V6M  [C_0603]  154.53 122.47 90 top
PC1086  22U_0603_6.3V6M  [C_0603]  153.32 122.47 90 top
PC1087  22U_0603_6.3V6M  [C_0603]  153.32 122.47 90 bottom
PC1088  22U_0603_6.3V6M  [C_0603]  110.93 110.94 270 bottom
PC1089  1U_0201_6.3V6M  [C_0201]  152.04 104.79 0 top
PC1090  1U_0201_6.3V6M  [C_0201]  163.74 94.18 180 top
PC1091  330U_D2_2.5VM_R9M  [C_D2]  159.9 117.24 90 bottom
PC1092  330U_D3_2.5VY_R6M  [C_D3]  157.18 99.96 180 top
PC1093  330U_D3_2.5VY_R6M  [C_D3]  159.9 117.24 90 top
PC1094  330U_D3_2.5VY_R6M  [C_D3]  155.66 119.07 180 top
PC1096  100P_0201_25V8J  [C_0201]  151.42 105.36 180 top
PC1097  100P_0201_25V8J  [C_0201]  149.63 105.36 0 top
PC1098  100P_0201_25V8J  [C_0201]  122.16 114.15 0 bottom
PC1099  100P_0201_25V8J  [C_0201]  162.85 119.4 0 top
PC1100  100P_0201_25V8J  [C_0201]  122.16 113.52 0 bottom
PC1101  22U_0603_6.3V6M  [C_0603]  121.41 85.82 270 top
PC1102  22U_0603_6.3V6M  [C_0603]  128.89 102.95 90 top
PC1103  22U_0603_6.3V6M  [C_0603]  122.61 85.82 270 bottom
PC1104  22U_0603_6.3V6M  [C_0603]  127.68 102.94 90 bottom
PC1105  22U_0603_6.3V6M  [C_0603]  147.44 98.12 0 top
PC1106  22U_0603_6.3V6M  [C_0603]  143.95 99.32 90 top
PC1107  22U_0603_6.3V6M  [C_0603]  144.65 98.37 270 top
PC1108  22U_0603_6.3V6M  [C_0603]  120.2 85.82 270 bottom
PC1109  22U_0603_6.3V6M  [C_0603]  147.44 101.74 0 top
PC1110  22U_0603_6.3V6M  [C_0603]  145.85 98.37 270 top
PC1111  22U_0603_6.3V6M  [C_0603]  127.67 102.95 90 top
PC1112  22U_0603_6.3V6M  [C_0603]  143.95 103.07 270 top
PC1113  22U_0603_6.3V6M  [C_0603]  120.2 85.82 270 top
PC1114  22U_0603_6.3V6M  [C_0603]  147.44 99.32 0 top
PC1115  22U_0603_6.3V6M  [C_0603]  147.44 102.94 0 top
PC1116  22U_0603_6.3V6M  [C_0603]  147.44 100.53 0 top
PC1117  22U_0603_6.3V6M  [C_0603]  128.89 102.94 90 bottom
PC1118  22U_0603_6.3V6M  [C_0603]  146.36 99.32 90 top
PC1119  22U_0603_6.3V6M  [C_0603]  145.22 105.1 180 top
PC1120  22U_0603_6.3V6M  [C_0603]  121.41 85.82 270 bottom
PC1121  22U_0603_6.3V6M  [C_0603]  145.16 103.07 270 top
PC1122  22U_0603_6.3V6M  [C_0603]  146.36 103.07 270 top
PC1123  22U_0603_6.3V6M  [C_0603]  145.16 99.32 90 top
PC1131  1U_0201_6.3V6M  [C_0201]  147.8 104.79 180 top
PC1132  1U_0201_6.3V6M  [C_0201]  146.01 105.36 0 top
PC1133  1U_0201_6.3V6M  [C_0201]  130.35 103.6 90 bottom
PC1134  1U_0201_6.3V6M  [C_0201]  129.78 103.6 90 bottom
PC1135  1U_0201_6.3V6M  [C_0201]  143.06 102.35 270 top
PC1136  1U_0201_6.3V6M  [C_0201]  148.17 97.23 0 top
PC1137  1U_0201_6.3V6M  [C_0201]  143.06 106.03 270 top
PC1138  1U_0201_6.3V6M  [C_0201]  147.8 105.36 180 top
PC1139  1U_0201_6.3V6M  [C_0201]  146.01 104.79 0 top
PC1140  1U_0201_6.3V6M  [C_0201]  131.49 103.6 90 bottom
PC1141  1U_0201_6.3V6M  [C_0201]  130.92 103.6 90 bottom
PC1142  330U_D3_2.5VY_R6M  [C_D3]  124.73 98.9 90 bottom
PC1143  330U_D3_2.5VY_R6M  [C_D3]  124.72 98.9 90 top
PC1146  100P_0201_25V8J  [C_0201]  148.42 105.36 0 top
PC1147  100P_0201_25V8J  [C_0201]  148.42 104.79 0 top
PC1151  22U_0603_6.3V6M  [C_0603]  166.11 133.36 180 bottom
PC1152  22U_0603_6.3V6M  [C_0603]  166.94 102.84 180 top
PC1153  22U_0603_6.3V6M  [C_0603]  167.64 97.04 0 top
PC1154  22U_0603_6.3V6M  [C_0603]  166.11 133.36 180 top
PC1155  22U_0603_6.3V6M  [C_0603]  167 101.61 180 top
PC1156  22U_0603_6.3V6M  [C_0603]  166.11 132.09 180 top
PC1157  22U_0603_6.3V6M  [C_0603]  166.12 130.86 180 top
PC1158  22U_0603_6.3V6M  [C_0603]  166.11 132.09 180 bottom
PC1159  22U_0603_6.3V6M  [C_0603]  167 100.4 180 top
PC1160  22U_0603_6.3V6M  [C_0603]  166.09 130.88 180 bottom
PC1161  22U_0603_6.3V6M  [C_0603]  167.64 98.24 0 top
PC1166  100P_0201_25V8J  [C_0201]  166.34 103.73 180 top
PC1167  100P_0201_25V8J  [C_0201]  166.78 105.36 180 top
PC1168  100P_0201_25V8J  [C_0201]  165.91 129.03 180 top
PC1169  18p_0402_50V6  [C_0402]  166.2 134.43 180 top
PC1170  22P_0402_50V8J  [C_0402]  167.38 134.16 90 top
PC1171  0.1U_0402_25V6  [C_0402]  165.98 129.78 180 top
PC1200  1000P_0402_50V7K  [C_0402]  150.38 122.98 90 top
PC1201  0.1U_0402_25V6  [C_0402]  151.3 122.98 90 top
PC1202  18p_0402_50V6  [C_0402]  152.22 123.01 90 top
PC1627  68U_D_20VM_R55M  [C_D]  96.06 88.43 180 bottom
PC3001  82P_0201_50V8J  [C_0201]  75.75 35.57 270 top
PC3002  0.01UF 25V +-10% X7R 0402  [C_0402]  71.78 33.08 180 top
PC3003  82P_0201_50V8J  [C_0201]  72.12 36.54 0 top
PC3004  82P_0201_50V8J  [C_0201]  67.14 32.99 0 top
PC3005  0.22U_0402_10V K  [C_0402]  69.74 36.7 0 top
PC3008  1U_0201_6.3V6M  [C_0201]  72.4 30.9 270 top
PC3009  1U_0201_6.3V6M  [C_0201]  73.95 33.73 180 top
PC3010  1U_0201_6.3V6M  [C_0201]  68.59 31.58 180 top
PC3011  1U_0201_6.3V6M  [C_0201]  68.59 30.95 180 top
PD1  CEST523NC5VB_SOT-523-3  [TVNST52302AB0_SOT523-3]  150.75 41.09 270 top
PD2  CEST523NC5VB_SOT-523-3  [TVNST52302AB0_SOT523-3]  150.75 43.13 270 top
PD3  BAS40CW_SOT323-3  [DB3J315E0L_SMINI3-F2-B3]  237.8 118.5 180 top
PD4  AZ5125-02S.R7G_SOT23-3  [PESD5V0U2BT_SOT23-3]  72.96 120.7 0 top
PD5  S SCH DIO 5A 100V 15UA 0.88V TO227-3  [PDS5100H-13_POWERDI5-3]  82.95 115.24 90 bottom
PD700  SDMK0340L-7-F_SOD323-2~D  [SDMK0340L-7-F_SOD323-2]  78.04 50.25 90 top
PD701  -  [SMF4L22A_SOD123FL2]  94.87 43.63 0 bottom
PD702  SDMK0340L-7-F_SOD323-2~D  [SDMK0340L-7-F_SOD323-2]  80.96 50.25 90 top
PD704  -  [RB520SM-30T2R_EMD2-2]  79.5 50.25 90 top
PD705  -  [BAT54CW_SOT323-3]  73.33 46.77 180 bottom
PD800  -  [BAT54CW_SOT323-3]  61.59 82.12 90 bottom
PD801  S SCH DIO 5A 100V 15UA 0.88V TO227-3  [PDS5100H-13_POWERDI5-3]  78.4 106.25 180 top
PD802  -  [SDMK0340L-7-F_SOD323-2]  63.69 87.89 270 bottom
PD803  -  [BAT54CW_SOT323-3]  67.64 115.4 0 top
PD3000  -  [BAT54CW_SOT323-3]  68.07 36.55 180 top
PD3001  -  [RB520SM-30T2R_EMD2-2]  74.86 35.89 270 top
PD3002  -  [RB520SM-30T2R_EMD2-2]  69.22 35.35 270 top
PH601  470K_0402_5%_B25/50 4700K  [R_0402]  119.79 103.31 90 bottom
PH602  10K_0402_5%_B25/50 4250K  [R_0402]  121.22 107.82 90 bottom
PH603  470K_0402_5%_B25/50 4700K  [R_0402]  109.66 91.7 0 bottom
PH604  10KB_0402_5%  [R_0402]  169.91 129.49 0 top
PH605  10K_0402_5%_B25/50 4250K  [R_0402]  114.98 83.51 0 bottom
PJP1  PAD-OPEN1x1m  [JUMP_43X39]  196.22 133.33 270 top
PJP2  PAD-OPEN1x1m  [JUMP_43X39]  190.84 133.17 270 top
PJP3  PAD-OPEN1x3m  [JUMP_43X118]  188.19 129.99 180 top
PJP8  PAD-OPEN 1x3m  [JUMP_43X118]  66.36 97.79 90 bottom
PJP12  PAD-OPEN1x1m  [JUMP_43X39]  146.95 133.53 0 top
PJP14  PAD-OPEN1x1m  [JUMP_43X39]  287 29.16 0 top
PJP15  PAD-OPEN1x1m  [JUMP_43X39]  274.07 56.46 180 top
PJP16  PAD-OPEN1x1m  [JUMP_43X39]  268.3 57.41 180 top
PJP17  PAD-OPEN1x2m  [JUMP_43X79]  274.44 59.81 270 top
PJP18  PAD-OPEN1x1m  [JUMP_43X39]  268.3 59.64 180 top
PJP19  PAD-OPEN1x1m  [JUMP_43X39]  288.09 61.4 90 top
PJP20  PAD-OPEN1x1m  [JUMP_43X39]  261.12 94.31 180 top
PJP22  PAD-OPEN1x1m  [JUMP_43X39]  248.6 85.09 90 top
PJP31  PAD-OPEN1x3m  [JUMP_43X118]  266.49 27.26 90 top
PJP32  PAD-OPEN1x1m  [JUMP_43X39]  239.83 34.07 270 top
PJP33  PAD-OPEN1x1m  [JUMP_43X39]  258.24 33.41 0 bottom
PJP34  PAD-OPEN1x2m  [JUMP_43X79]  250.86 41.09 180 top
PJP35  PAD-OPEN1x1m  [JUMP_43X39]  185.85 36.84 0 top
PJP36  PAD-OPEN1x2m  [JUMP_43X79]  264.6 63.62 270 top
PJP37  PAD-OPEN1x1m  [JUMP_43X39]  275.52 94.23 90 top
PJP38  PAD-OPEN1x1m  [JUMP_43X39]  222.45 82.94 180 top
PJP39  PAD-OPEN1x3m  [JUMP_43X118]  223.64 88.87 90 top
PJP40  PAD-OPEN1x2m  [JUMP_43X79]  271.97 64.05 270 top
PJP41  PAD-OPEN1x3m  [JUMP_43X118]  277.17 87.49 270 top
PJP42  PAD-OPEN1x1m  [JUMP_43X39]  277.55 63.14 270 top
PJP100  PAD-OPEN 1x2m~D  [JUMP_43X79]  196.8 31.19 0 bottom
PJP101  PAD-OPEN 1x2m~D  [JUMP_43X79]  84.05 71.07 180 bottom
PJP102  -  [JUMP_43X118]  218.58 33.28 0 bottom
PJP103  -  [JUMP_43X118]  75.38 79.82 135 bottom
PJP200  -  [JUMP_43X118]  97.34 59 0 top
PJP201  -  [JUMP_43X39]  95.3 65.42 0 top
PJP202  PAD-OPEN 1x2m~D  [JUMP_43X79]  92.13 73.39 270 bottom
PJP301  PAD-OPEN 1x2m~D  [JUMP_43X79]  234.21 124.82 90 top
PJP302  -  [JUMP_43X118]  219.9 128.51 270 top
PJP401  -  [JUMP_43X79]  113.09 74.45 90 top
PJP402  -  [JUMP_43X79]  201.1 130.42 270 top
PJP403  PAD-OPEN1x1m  [JUMP_43X39]  101.58 77.42 0 top
PJP404  PAD-OPEN1x1m  [JUMP_43X39]  212.59 129.92 90 top
PJP501  PAD-OPEN1x1m  [JUMP_43X39]  206.19 114.18 180 bottom
PJP502  PAD-OPEN1x1m  [JUMP_43X39]  198.64 109.17 180 bottom
PJP503  PAD-OPEN1x1m  [JUMP_43X39]  280.55 95.7 180 top
PJP504  PAD-OPEN1x1m  [JUMP_43X39]  287.51 94.94 0 top
PJP505  PAD-OPEN1x1m  [JUMP_43X39]  241.2 63.67 270 top
PJP506  PAD-OPEN1x1m  [JUMP_43X39]  241.39 56.43 270 top
PJP601  PAD-OPEN 4x4m  [JUMP_43X118]  96.25 83.58 270 bottom
PJP602  PAD-OPEN 1x2m~D  [JUMP_43X79]  103.73 93.16 180 bottom
PJP603  PAD-OPEN1x1m  [JUMP_43X39]  179.24 129.17 0 bottom
PJP700  PAD-OPEN 4x4m  [JUMP_43X118-NPM]  95.56 39.1 270 bottom
PJPDC1  CVILU_CI0805M1HRC-NH  [CVILU_CI0805M1HRC-NH_5P-T]  66.12 126.45 270 bottom
PL1  FBMJ4516HS720NT_2P  [TAIYO_FBMJ4516HS720NT_2P]  138.52 39.22 180 top
PL2  FBMJ4516HS720NT_2P  [TAIYO_FBMJ4516HS720NT_2P]  138.54 36.96 180 top
PL3  BLM15AG102SN1D_2P  [MURAT_BLM15AG102SN1D_2P]  73.97 125.47 270 top
PL4  FBMJ4516HS720NT_2P  [TAIYO_FBMJ4516HS720NT_2P]  70.54 119.89 270 bottom
PL100  1.5UH_9A_20%_7X7X3_M  [L_7X7X3_M_2P]  208.49 33.09 0 bottom
PL101  1.5UH_9A_20%_7X7X3_M  [L_7X7X3_M_2P]  81.97 76.3 90 bottom
PL201  1UH_PCMB063T-1R0MS_12A_20%  [CYNTE_PCMB063T-1R0MS_2P]  88.47 59.9 0 bottom
PL301  0.68UH_7.9A_20%_5X5X3_M  [L_5X5X3_M_2P]  227.79 132.03 180 top
PL402  1UH_1277AS-H-1R0N-P2_3.3A_30%  [MAG_MLV-FY12N1R0M-O1L_2P]  109.66 76.3 270 top
PL404  1UH_1277AS-H-1R0N-P2_3.3A_30%  [MAG_MLV-FY12N1R0M-O1L_2P]  204.78 129.33 90 top
PL405  3A_Z120_40M_0603_2P  [3A_Z120_0603_2P]  101.39 75.51 0 top
PL406  3A_Z120_40M_0603_2P  [3A_Z120_0603_2P]  214.5 129.75 90 top
PL501  1UH_1277AS-H-1R0N-P2_3.3A_30%  [MAG_MLV-FY12N1R0M-O1L_2P]  199.11 113.58 270 bottom
PL502  3A_Z120_40M_0603_2P  [3A_Z120_0603_2P]  206.77 112.34 180 bottom
PL602  9A Z80 10M 1812_2P  [9A_Z80_1812_2P-NPM]  96.25 84.93 270 bottom
PL610  0.15UH_MMD-06CZER15MEX5L__35A_20%  [L_7X7X3_M]  116.2 112.9 270 bottom
PL612  0.15UH_MMD-06CZER15MEX5L__35A_20%  [L_7X7X3_M]  117.71 87.77 180 bottom
PL613  0.15UH_MMD-06CZER15MEX5L__35A_20%  [L_7X7X3_M]  107.1 113.9 180 bottom
PL614  0.47UH_MMD05CZR47M_12A_20%  [MAG_MMD05CZR47M_4P]  169.78 132.85 0 top
PL700  1UH_PCMB051H-1R0MS_8A_20%  [CYNTE_PCMB051H-1R0MS_2P]  95.56 40.73 270 bottom
PL701  2.2UH_PCMB103T-2R2MS_13A_20%  [CYNTE_PCMB103T-2R2MS_2P]  108.19 36.56 0 bottom
PL800  5A_Z80_20M_0805_2P  [TAI-T_HCB2012KF-121T50_2P]  21.39 95.29 270 top
PL801  5A_Z80_20M_0805_2P  [TAI-T_HCB2012KF-121T50_2P]  23.17 95.29 270 top
PQ1  L2N7002DW1T1G 2N SC88-6  [DMN65D8LDW-7_SOT363-6]  86.18 117.55 180 top
PQ2  -  [FDV301N-G_SOT23-3]  76.14 126.97 270 top
PQ3  LMBT3904WT1G NPN SC70-3  [MMST3904-7-F_SOT323-3]  78.35 123.64 90 top
PQ4  EMZB08P03V_EDFN3X3-8-5  [FDMC6679AZ_MLP8-5]  79.58 113.18 180 bottom
PQ5  AO3409 P-CHANNEL SOT-23  [AO3409_SOT23-3]  74.73 112.24 0 bottom
PQ6  L2N7002WT1G 1N SC-70-3  [DMN65D8LW-7_SOT323-3]  81.95 118.61 180 top
PQ7  L2N7002WT1G 1N SC-70-3  [DMN65D8LW-7_SOT323-3]  78.61 109.04 270 bottom
PQ8  L2N7002WT1G 1N SC-70-3  [DMN65D8LW-7_SOT323-3]  92.08 121.17 180 bottom
PQ9  S TR EMZB08P03V 1P EDFN3X3-8  [FDMC6679AZ_MLP8-5]  77.2 117.58 90 bottom
PQ10  L2N7002DW1T1G 2N SC88-6  [DMN65D8LDW-7_SOT363-6]  88.21 119.44 90 bottom
PQ11  AO3409 P-CHANNEL SOT-23  [AO3409_SOT23-3]  78.67 118.79 0 top
PQ12  L2N7002WT1G 1N SC-70-3  [DMN65D8LW-7_SOT323-3]  86.88 118.75 180 bottom
PQ13  L2N7002WT1G 1N SC-70-3  [DMN65D8LW-7_SOT323-3]  241.2 125.53 0 top
PQ614  AONH36334 2N DFN3X3A  [AON7934_DFN3X3A8-10]  176.88 131.22 0 top
PQ700  AOE6936_DFN5X6E8-10  [AOE6930_DFN5X6E8-10]  99.19 34.28 90 bottom
PQ701  AOE6936_DFN5X6E8-10  [AOE6930_DFN5X6E8-10]  126.26 39.76 270 bottom
PQ702  EMZB08P03V_EDFN3X3-8-5  [FDMC6679AZ_MLP8-5]  130.21 39.44 270 top
PQ703  2N7002KW 1N SOT323-3  [DMN65D8LW-7_SOT323-3]  76.13 47.89 0 bottom
PQ800  S TR EMZB08P03V 1P EDFN3X3-8  [FDMC6679AZ_MLP8-5]  69.91 111.13 270 top
PQ801  EMZB08P03V_EDFN3X3-8-5  [FDMC6679AZ_MLP8-5]  76.64 109.72 90 top
PQ802  L2N7002DW1T1G 2N SC88-6  [DMN65D8LDW-7_SOT363-6]  93.01 79.64 0 top
PQ803  AO3409 P-CHANNEL SOT-23  [AO3409_SOT23-3]  92.51 84.25 0 top
PQ804  L2N7002DW1T1G 2N SC88-6  [DMN65D8LDW-7_SOT363-6]  83.23 94.88 0 bottom
PQ805  AO3409 P-CHANNEL SOT-23  [AO3409_SOT23-3]  83.45 110.59 90 top
PQ806  L2N7002DW1T1G 2N SC88-6  [DMN65D8LDW-7_SOT363-6]  92.13 116.26 90 top
PQ807  L2N7002WT1G 1N SC-70-3  [DMN65D8LW-7_SOT323-3]  80.2 98.18 0 bottom
PQ808  L2N7002DW1T1G 2N SC88-6  [DMN66D0LDW-7_SOT363-6]  41.19 88.28 0 top
PQ809  L2N7002DW1T1G 2N SC88-6  [DMN66D0LDW-7_SOT363-6]  43.73 88.28 0 top
PQ810  L2N7002DW1T1G 2N SC88-6  [DMN66D0LDW-7_SOT363-6]  46.27 88.28 0 top
PQ811  L2N7002DW1T1G 2N SC88-6  [DMN66D0LDW-7_SOT363-6]  48.81 88.28 0 top
PQ812  L2N7002WT1G 1N SC-70-3  [DMN65D8LW-7_SOT323-3]  51.55 86.43 270 top
PQ813  L2N7002DW1T1G 2N SC88-6  [DMN65D8LDW-7_SOT363-6]  65.52 89.64 0 bottom
PQ814  L2N7002WT1G 1N SC-70-3  [DMN65D8LW-7_SOT323-3]  90.74 81.8 0 top
PQ3000  L2N7002DW1T1G 2N SC88-6  [DMN65D8LDW-7_SOT363-6]  69.57 31.95 270 top
PR1  100K_0402_5%  [R_0402]  150.25 39.7 180 top
PR2  1K_0402_5%  [R_0402]  239.4 121.61 180 top
PR3  0_0402_5%  [R_0402]  76.18 129.36 0 top
PR4  2.2K_0402_5%  [R_0402]  93.81 118.06 180 bottom
PR5  33_0402_5%  [R_0402]  79.94 127.91 270 top
PR6  100K_0402_1%  [R_0402]  75.37 125.5 270 top
PR7  10K_0402_1%  [R_0402]  79.51 124.6 180 top
PR8  15K_0402_1%  [R_0402]  75.37 123.85 270 top
PR9  10M_0402_5%  [R_0402]  238.53 122.52 180 top
PR10  300K_0402_5%  [R_0402]  73.39 108.4 0 bottom
PR11  499K_0402_1%  [R_0402]  78.24 110.82 180 bottom
PR12  1M_0402_5%  [R_0402]  75.04 118.7 90 bottom
PR13  4.7K_0805_5%  [R_0805]  72.55 118.59 90 bottom
PR14  100K_0402_5%  [R_0402]  75.99 115.97 180 bottom
PR15  100K_0402_5%  [R_0402]  75.04 108.4 0 bottom
PR16  49.9K_0402_1%  [R_0402]  77.33 110.06 0 bottom
PR17  100K_0402_5%  [R_0402]  88.32 117.75 270 top
PR18  1M_0402_5%  [R_0402]  80.12 118.03 0 top
PR19  0_0402_5%  [R0402_0OHM]  87.56 117.75 270 top
PR20  0_0402_5%  [R0402_0OHM]  81.72 109.75 270 bottom
PR22  0_0402_5%  [R0402_0OHM]  82.84 121.61 180 top
PR24  100K_0402_5%  [R_0402]  82.66 108.91 0 bottom
PR25  0_0402_5%  [R0402_0OHM]  85.54 114.56 180 top
